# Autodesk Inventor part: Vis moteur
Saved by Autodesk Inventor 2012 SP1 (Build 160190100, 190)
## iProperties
Created: 2014-12
Part Number: Vis moteur
Material: Default
Document SubType Name: Modeling
Designer: Bruno
Density: 1 g/cm^3
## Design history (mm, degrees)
node "Vis moteur1"
node "Vis moteur"
node "Base1"
